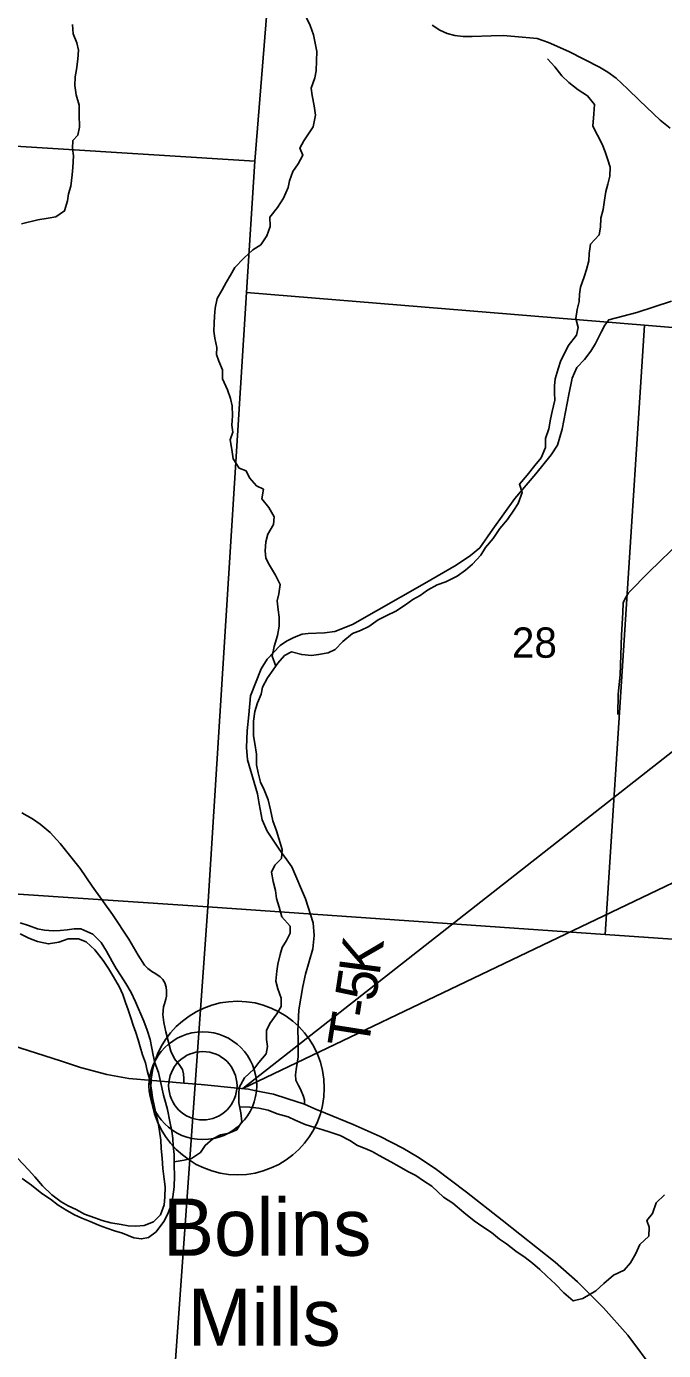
# Model space of a CAD drawing. Extents: x -8.2 to 34, y 0 to 22.
# Drawn here: x 5.17 to 6.05, y 17.043 to 18.871 of the extents above; entities that cross this region are included whole.
import ezdxf

# ---------------------------------------------------------------- set-up
doc = ezdxf.new("R2010")
doc.units = 0
for name, color, linetype in [('Default', 7, 'Continuous'), ('GM_X_Corporation', 7, 'Continuous'), ('GM_X_County_Road', 7, 'Continuous'), ('GM_X_Major_River', 7, 'Continuous'), ('GM_X_Minor_River', 7, 'Continuous'), ('GM_X_Section_Text', 7, 'Continuous'), ('GM_X_State_Route', 7, 'Continuous'), ('GM_X_Township_Road', 7, 'Continuous'), ('GM_X_Township_Road_Text', 7, 'Continuous'), ('GM_X_Unincorporated', 7, 'Continuous'), ('GM_X_Unincorporated_Location', 7, 'Continuous'), ('GM_X_Unincorporated_Text', 7, 'Continuous'), ('GM_X_US_Route', 7, 'Continuous')]:
    doc.layers.add(name, color=color, linetype=linetype)

msp = doc.modelspace()

# ---------------------------------------------------------------- linework, layer by layer
at = {"layer": 'Default'}
msp.add_lwpolyline([(6.2543, 18.0203), (5.4694, 17.4047), (6.2543, 17.7803)], close=True, dxfattribs=at)
msp.add_circle((5.4619, 17.4055), 0.1198, dxfattribs=at)
at = {"layer": 'GM_X_Corporation'}
for points in [[(4.5379, 19.7849), (5.5693, 19.7272), (5.5363, 19.3151), (5.5032, 18.9017), (5.4857, 18.6849), (4.465, 18.749)], [(5.4857, 18.6849), (5.4744, 18.5035), (5.4208, 17.6558), (4.3947, 17.7241), (4.465, 18.749)], [(5.4744, 18.5035), (6.0241, 18.4583), (5.9698, 17.6173), (5.4208, 17.6558)], [(5.4208, 17.6558), (5.3461, 16.6043), (4.3249, 16.693), (4.3947, 17.7241)]]:
    msp.add_lwpolyline(points, close=True, dxfattribs=at)
msp.add_lwpolyline([(6.4559, 17.7803), (6.4419, 17.5848), (5.9698, 17.6173), (6.0241, 18.4583), (6.5013, 18.4191), (6.4729, 18.0203)], dxfattribs=at)
at = {"layer": 'GM_X_County_Road'}
msp.add_lwpolyline([(5.7307, 18.8725), (5.7413, 18.8657), (5.7516, 18.861), (5.7619, 18.8582), (5.7735, 18.8567), (5.786, 18.8571), (5.8123, 18.8579), (5.8287, 18.8581), (5.8449, 18.8569), (5.8757, 18.8542), (5.8915, 18.8487), (5.9192, 18.8361), (5.9619, 18.8147), (5.9733, 18.8078), (5.9846, 18.7992), (6.0003, 18.7845), (6.0168, 18.7688), (6.0456, 18.7413), (6.0593, 18.7306)], dxfattribs=at)
at = {"layer": 'GM_X_Major_River'}
for points in [[(5.1616, 17.6182), (5.1738, 17.6125), (5.1859, 17.6079), (5.2007, 17.6045), (5.2152, 17.6068), (5.2281, 17.6113), (5.2425, 17.6113), (5.2531, 17.6071), (5.2649, 17.5961), (5.2763, 17.5817), (5.2838, 17.5707), (5.2907, 17.5589), (5.299, 17.5448), (5.3036, 17.5346), (5.307, 17.5236), (5.3111, 17.5133), (5.3145, 17.5023), (5.3179, 17.4921), (5.3213, 17.4822), (5.3248, 17.4719), (5.3274, 17.4625), (5.3308, 17.4515), (5.3346, 17.4401), (5.3372, 17.4298), (5.3406, 17.4165), (5.3429, 17.4032), (5.3444, 17.3922), (5.3467, 17.3812), (5.3493, 17.371), (5.352, 17.3596), (5.3542, 17.3459), (5.3558, 17.3334), (5.3565, 17.322), (5.358, 17.3087), (5.3587, 17.2943), (5.3606, 17.2799), (5.3618, 17.2689), (5.3617, 17.2548), (5.3606, 17.2442), (5.3556, 17.2306), (5.3461, 17.2207), (5.3332, 17.2158), (5.3215, 17.215), (5.3108, 17.2154), (5.3013, 17.2169), (5.2869, 17.2192), (5.2748, 17.2226), (5.2649, 17.2264), (5.2508, 17.2314), (5.2391, 17.2378), (5.2281, 17.2428), (5.2186, 17.2485), (5.2057, 17.258), (5.1928, 17.2705), (5.1818, 17.2827), (5.1731, 17.2925), (5.1503, 17.3169)], [(5.1643, 17.2808), (5.1776, 17.2713), (5.1916, 17.2599), (5.2038, 17.2519), (5.2144, 17.2436), (5.2262, 17.2363), (5.2368, 17.2306), (5.2467, 17.2257), (5.2584, 17.2211), (5.2713, 17.2158), (5.2816, 17.212), (5.2918, 17.2086), (5.3032, 17.2052), (5.3188, 17.1987), (5.3294, 17.1972), (5.3389, 17.1994), (5.3495, 17.207), (5.3602, 17.2214), (5.3651, 17.2309), (5.3693, 17.2415), (5.3728, 17.2552), (5.3743, 17.2693), (5.3747, 17.2844), (5.3743, 17.2989), (5.3743, 17.3137), (5.3732, 17.3258), (5.3725, 17.3357), (5.3713, 17.3459), (5.3683, 17.3592), (5.3653, 17.3759), (5.3623, 17.3858), (5.3596, 17.3956), (5.3555, 17.4146), (5.3528, 17.4271), (5.3479, 17.4404), (5.3456, 17.4507), (5.3437, 17.4605), (5.3415, 17.4723), (5.3373, 17.4852), (5.3324, 17.4978), (5.321, 17.5243), (5.3149, 17.5372), (5.3077, 17.5498), (5.3013, 17.56), (5.2945, 17.5703), (5.2888, 17.5801), (5.2812, 17.5942), (5.2736, 17.6063), (5.2619, 17.6177), (5.2455, 17.6253), (5.2361, 17.625), (5.2266, 17.6238), (5.2171, 17.6231), (5.2072, 17.6223), (5.1954, 17.6235), (5.1859, 17.625), (5.1734, 17.6296), (5.1616, 17.6337)]]:
    msp.add_lwpolyline(points, dxfattribs=at)
at = {"layer": 'GM_X_Minor_River'}
for points in [[(5.5664, 18.7324), (5.5694, 18.7482), (5.5679, 18.7611), (5.5652, 18.7756), (5.5637, 18.7858), (5.5686, 18.7998), (5.5705, 18.8097), (5.5708, 18.8234), (5.5716, 18.8363), (5.567, 18.859), (5.562, 18.8723), (5.5575, 18.8818), (5.5461, 18.8943), (5.537, 18.9083), (5.5287, 18.9212), (5.5199, 18.9341), (5.5112, 18.9455), (5.5048, 18.9561), (5.4995, 18.9663), (5.4968, 18.9762), (5.4949, 18.9887)], [(5.2438, 18.7318), (5.243, 18.7492), (5.243, 18.7621), (5.2392, 18.7765), (5.2373, 18.7891), (5.2376, 18.8012), (5.2395, 18.8114), (5.2414, 18.8255), (5.2421, 18.838), (5.2398, 18.8482), (5.2349, 18.8608), (5.2338, 18.8733)], [(5.9526, 18.7332), (5.9541, 18.7503), (5.9548, 18.7632), (5.945, 18.775), (5.9325, 18.7833), (5.9196, 18.7932), (5.9097, 18.8027), (5.9003, 18.8152), (5.89, 18.8262)], [(5.8919, 18.3152), (5.8942, 18.3289), (5.8964, 18.3395), (5.9002, 18.355), (5.8994, 18.3649), (5.8998, 18.3748), (5.9006, 18.3842), (5.9047, 18.3983), (5.9081, 18.4085), (5.9187, 18.4298), (5.93, 18.4446), (5.9323, 18.4552), (5.9289, 18.4677), (5.9307, 18.4802), (5.9338, 18.4912), (5.9341, 18.5011), (5.9353, 18.511), (5.9405, 18.525), (5.9436, 18.5352), (5.9469, 18.5474), (5.9477, 18.5572), (5.9492, 18.5705), (5.9613, 18.583), (5.9632, 18.5937), (5.9635, 18.6062), (5.9666, 18.6183), (5.9688, 18.6312), (5.9703, 18.643), (5.9733, 18.6532), (5.976, 18.6642), (5.9763, 18.6767), (5.9729, 18.6881), (5.9695, 18.6976), (5.9653, 18.7082), (5.9526, 18.7332)], [(5.1635, 18.5982), (5.1863, 18.604), (5.2006, 18.6063), (5.2112, 18.6082), (5.223, 18.6161), (5.2271, 18.6302), (5.2286, 18.6397), (5.2316, 18.6503), (5.2335, 18.6658), (5.2343, 18.6761), (5.2354, 18.692), (5.2342, 18.7022), (5.2346, 18.7132), (5.2413, 18.7206), (5.2438, 18.7318)], [(5.5146, 17.9877), (5.5097, 18.0014), (5.5124, 18.0147), (5.5173, 18.0303), (5.5195, 18.0428), (5.5195, 18.0553), (5.518, 18.0655), (5.5165, 18.0781), (5.5191, 18.0875), (5.521, 18.1004), (5.5145, 18.1133), (5.5062, 18.127), (5.5009, 18.1368), (5.5001, 18.147), (5.5012, 18.1596), (5.5038, 18.1698), (5.5114, 18.1831), (5.5125, 18.1941), (5.5053, 18.2066), (5.4955, 18.2187), (5.4977, 18.232), (5.4882, 18.2365), (5.4784, 18.2479), (5.4738, 18.2574), (5.4643, 18.2611), (5.456, 18.274), (5.4541, 18.2869), (5.4518, 18.3002), (5.4556, 18.3108), (5.454, 18.3203), (5.4548, 18.3332), (5.4544, 18.3472), (5.4521, 18.3571), (5.4479, 18.3692), (5.4411, 18.3844), (5.4411, 18.3969), (5.4361, 18.4086), (5.4331, 18.4181), (5.4334, 18.4276), (5.4308, 18.4405), (5.4293, 18.4503), (5.4296, 18.4613), (5.43, 18.4708), (5.4311, 18.4818), (5.4337, 18.4955), (5.4409, 18.5072), (5.4462, 18.5175), (5.4523, 18.5274), (5.4583, 18.538), (5.4708, 18.5509), (5.4829, 18.5623), (5.4943, 18.5695), (5.5026, 18.5816), (5.5071, 18.5946), (5.5063, 18.6074), (5.5173, 18.6211), (5.5252, 18.6336), (5.532, 18.6484), (5.5335, 18.6579), (5.5381, 18.6708), (5.5456, 18.6811), (5.5521, 18.6932), (5.5479, 18.7027), (5.5536, 18.7128), (5.5664, 18.7324)], [(5.3743, 17.3035), (5.3882, 17.3061), (5.3985, 17.3081), (5.411, 17.3164), (5.417, 17.3263), (5.428, 17.3354), (5.4386, 17.3407), (5.4499, 17.3434), (5.4609, 17.3476), (5.4677, 17.3586), (5.4666, 17.3711), (5.4639, 17.3851), (5.4635, 17.3969), (5.4643, 17.4064), (5.4714, 17.4196), (5.4843, 17.4314), (5.4911, 17.4409), (5.5013, 17.4527), (5.5032, 17.4629), (5.5021, 17.4724), (5.502, 17.4849), (5.5066, 17.4944), (5.516, 17.5081), (5.5221, 17.5179), (5.5224, 17.5293), (5.5175, 17.5426), (5.5148, 17.5532), (5.516, 17.5669), (5.5175, 17.5763), (5.5209, 17.59), (5.5235, 17.5995), (5.5295, 17.609), (5.5348, 17.6192), (5.5348, 17.6287), (5.5231, 17.6419), (5.5196, 17.6552), (5.5158, 17.6673), (5.5143, 17.6783), (5.5109, 17.6905), (5.509, 17.7034), (5.5135, 17.7129), (5.5226, 17.7223), (5.5237, 17.7349), (5.5188, 17.75), (5.5157, 17.7606), (5.5108, 17.7743), (5.5073, 17.7894), (5.5043, 17.8035), (5.4986, 17.8171), (5.4937, 17.8277), (5.4906, 17.8406), (5.4883, 17.8516), (5.4879, 17.8664), (5.486, 17.8812), (5.4841, 17.8918), (5.4841, 17.9119), (5.4856, 17.9252), (5.4897, 17.9373), (5.4946, 17.9491), (5.4965, 17.9586), (5.5033, 17.9715), (5.5109, 17.9825), (5.5177, 17.992), (5.5268, 18.0026), (5.5366, 18.0075), (5.5506, 18.0038), (5.5639, 18.0023), (5.5738, 18.0038), (5.587, 18.0061), (5.5968, 18.0107), (5.6074, 18.0217), (5.6207, 18.0331), (5.6317, 18.0369), (5.643, 18.0426), (5.6563, 18.0517), (5.668, 18.0578), (5.6805, 18.0635), (5.6937, 18.0726), (5.704, 18.0798), (5.7142, 18.0855), (5.7244, 18.0928), (5.7376, 18.1), (5.7494, 18.1042), (5.7653, 18.1121), (5.7766, 18.1201), (5.7865, 18.1285), (5.7978, 18.141), (5.8043, 18.1516), (5.8148, 18.1642), (5.8239, 18.1778), (5.8345, 18.1904), (5.8436, 18.2029), (5.8496, 18.2124), (5.8549, 18.2276), (5.8511, 18.2389), (5.8617, 18.2515), (5.8723, 18.2648), (5.881, 18.2754), (5.8874, 18.2894), (5.887, 18.3019), (5.8919, 18.3152)], [(5.4649, 17.3797), (5.4791, 17.3791), (5.4912, 17.3776), (5.5041, 17.3749), (5.5166, 17.37), (5.5317, 17.3655), (5.5416, 17.361), (5.5552, 17.3553), (5.5685, 17.3511), (5.5784, 17.3481), (5.5912, 17.3443), (5.6037, 17.3398), (5.617, 17.333), (5.6276, 17.3262), (5.6382, 17.322), (5.6477, 17.3179), (5.6576, 17.3122), (5.6735, 17.3035), (5.6852, 17.2971), (5.697, 17.2903), (5.708, 17.2846), (5.7186, 17.2774), (5.7303, 17.2698), (5.7463, 17.2547), (5.7592, 17.2464), (5.7743, 17.2335), (5.7887, 17.2221), (5.7994, 17.2146), (5.8126, 17.2062), (5.8236, 17.1968), (5.8335, 17.1903), (5.846, 17.1801), (5.8593, 17.1714), (5.8691, 17.1638), (5.8794, 17.1548), (5.8888, 17.146), (5.901, 17.1347), (5.9127, 17.1226), (5.9256, 17.1116), (5.9389, 17.115), (5.9567, 17.1257), (5.9676, 17.1355), (5.9809, 17.1473), (5.996, 17.1542), (6.0047, 17.1644), (6.0119, 17.1769), (6.0176, 17.1895), (6.0301, 17.2012), (6.0304, 17.2134), (6.027, 17.2228), (6.0349, 17.2323), (6.0402, 17.2471), (6.0516, 17.2581)]]:
    msp.add_lwpolyline(points, dxfattribs=at)
at = {"layer": 'GM_X_State_Route'}
msp.add_lwpolyline([(5.3878, 17.4121), (5.3878, 17.418), (5.3875, 17.425), (5.386, 17.431), (5.3813, 17.4379), (5.3749, 17.446), (5.3696, 17.4562), (5.3631, 17.4829), (5.3603, 17.496), (5.3587, 17.5069), (5.3599, 17.5174), (5.3612, 17.5219), (5.3628, 17.528), (5.3639, 17.5322), (5.3637, 17.5395), (5.3632, 17.5448), (5.3615, 17.5506), (5.3589, 17.5553), (5.3549, 17.5588), (5.3489, 17.5633), (5.3435, 17.5664), (5.3381, 17.5707), (5.3336, 17.575), (5.3247, 17.5888), (5.3118, 17.611), (5.2894, 17.6451), (5.2611, 17.6843), (5.2445, 17.7087), (5.2168, 17.743), (5.2031, 17.7583), (5.1893, 17.7697), (5.1788, 17.7771), (5.1642, 17.7853)], dxfattribs=at)
at = {"layer": 'GM_X_Township_Road'}
for points in [[(5.5379, 18.0263), (5.5429, 18.0289), (5.5511, 18.032), (5.5593, 18.033), (5.5819, 18.0336), (5.5964, 18.0356), (5.6206, 18.0451), (5.7199, 18.1019), (5.7637, 18.1274), (5.7837, 18.1404), (5.7964, 18.1513), (5.8144, 18.1771), (5.8448, 18.2193), (5.8737, 18.2533), (5.8951, 18.2797), (5.9039, 18.2929), (5.9102, 18.315), (5.9196, 18.3628), (5.9238, 18.3854), (5.9304, 18.3999), (5.9409, 18.4113), (5.9496, 18.4225), (5.9562, 18.433), (5.9639, 18.4489), (5.9693, 18.4586), (5.9746, 18.4659), (6.0131, 18.4761), (6.0613, 18.4915)], [(5.9869, 17.9211), (5.9877, 17.9491), (5.9901, 17.9756), (5.9922, 18.0304), (5.9939, 18.062), (5.9943, 18.075), (5.9974, 18.0812), (6.0016, 18.0891), (6.0304, 18.1182), (6.075, 18.1612), (6.1033, 18.1855), (6.1554, 18.2157), (6.1775, 18.2279), (6.1846, 18.2327), (6.1915, 18.2375), (6.2031, 18.2503)], [(5.5546, 17.3832), (5.5546, 17.3893), (5.5532, 17.394), (5.5488, 17.4038), (5.5462, 17.4088), (5.5426, 17.4164), (5.5419, 17.4236), (5.5431, 17.4311), (5.5455, 17.4486), (5.5456, 17.4736), (5.545, 17.4839), (5.5467, 17.5136), (5.5521, 17.5454), (5.5557, 17.5626), (5.5659, 17.5975), (5.5679, 17.6159), (5.5662, 17.6335), (5.5558, 17.6665), (5.5368, 17.7108), (5.5192, 17.7352), (5.503, 17.76), (5.4961, 17.7759), (5.492, 17.7976), (5.4894, 17.8117), (5.4755, 17.8585), (5.4742, 17.8755), (5.4754, 17.8984), (5.4773, 17.9208), (5.4796, 17.9468), (5.4947, 17.9842), (5.5027, 17.9976), (5.5208, 18.0165), (5.5296, 18.0221), (5.5379, 18.0263)]]:
    msp.add_lwpolyline(points, dxfattribs=at)
at = {"layer": 'GM_X_Unincorporated'}
for radius in [0.0744, 0.0472]:
    msp.add_circle((5.414, 17.4087), radius, dxfattribs=at)
at = {"layer": 'GM_X_Unincorporated_Location'}
msp.add_line((5.414, 17.4087), (5.414, 17.4087), dxfattribs=at)
at = {"layer": 'GM_X_US_Route'}
for points in [[(5.0961, 17.4816), (5.2174, 17.4428), (5.2451, 17.434), (5.2815, 17.424), (5.3119, 17.4187), (5.3444, 17.4158), (5.3503, 17.4152), (5.3721, 17.4136), (5.3878, 17.4121)], [(5.3878, 17.4121), (5.4117, 17.4103), (5.4619, 17.4055), (5.4769, 17.4038), (5.485, 17.4022), (5.5116, 17.3968), (5.53, 17.391), (5.5546, 17.3832), (5.5687, 17.3768), (5.5836, 17.3709), (5.6214, 17.3551), (5.6591, 17.3387), (5.69, 17.3227), (5.7106, 17.3104), (5.7346, 17.2943), (5.7782, 17.2619), (5.8272, 17.2229), (5.9007, 17.1651), (5.9314, 17.1378), (5.9672, 17.1022), (6.0007, 17.0645), (6.0371, 17.0157)]]:
    msp.add_lwpolyline(points, dxfattribs=at)

# ---------------------------------------------------------------- texts
at = {"layer": 'GM_X_Section_Text'}
msp.add_text('28', height=0.04186, rotation=0, dxfattribs=at).set_placement((5.8407, 17.9994))
at = {"layer": 'GM_X_Township_Road_Text'}
for s, rotation, p in [('K', 82.4619, (5.6578, 17.5595)), ('5', 81.3195, (5.6523, 17.5236)), ('T', 81.0668, (5.6421, 17.4583)), ('-', 81.1185, (5.6487, 17.5004))]:
    msp.add_text(s, height=0.0568, rotation=rotation, dxfattribs=at).set_placement(p)
at = {"layer": 'GM_X_Unincorporated_Text'}
for s, p in [('Bolins', (5.359, 17.1739)), ('Mills', (5.3932, 17.0497))]:
    msp.add_text(s, height=0.07898, rotation=0, dxfattribs=at).set_placement(p)

doc.saveas('drawing.dxf')
